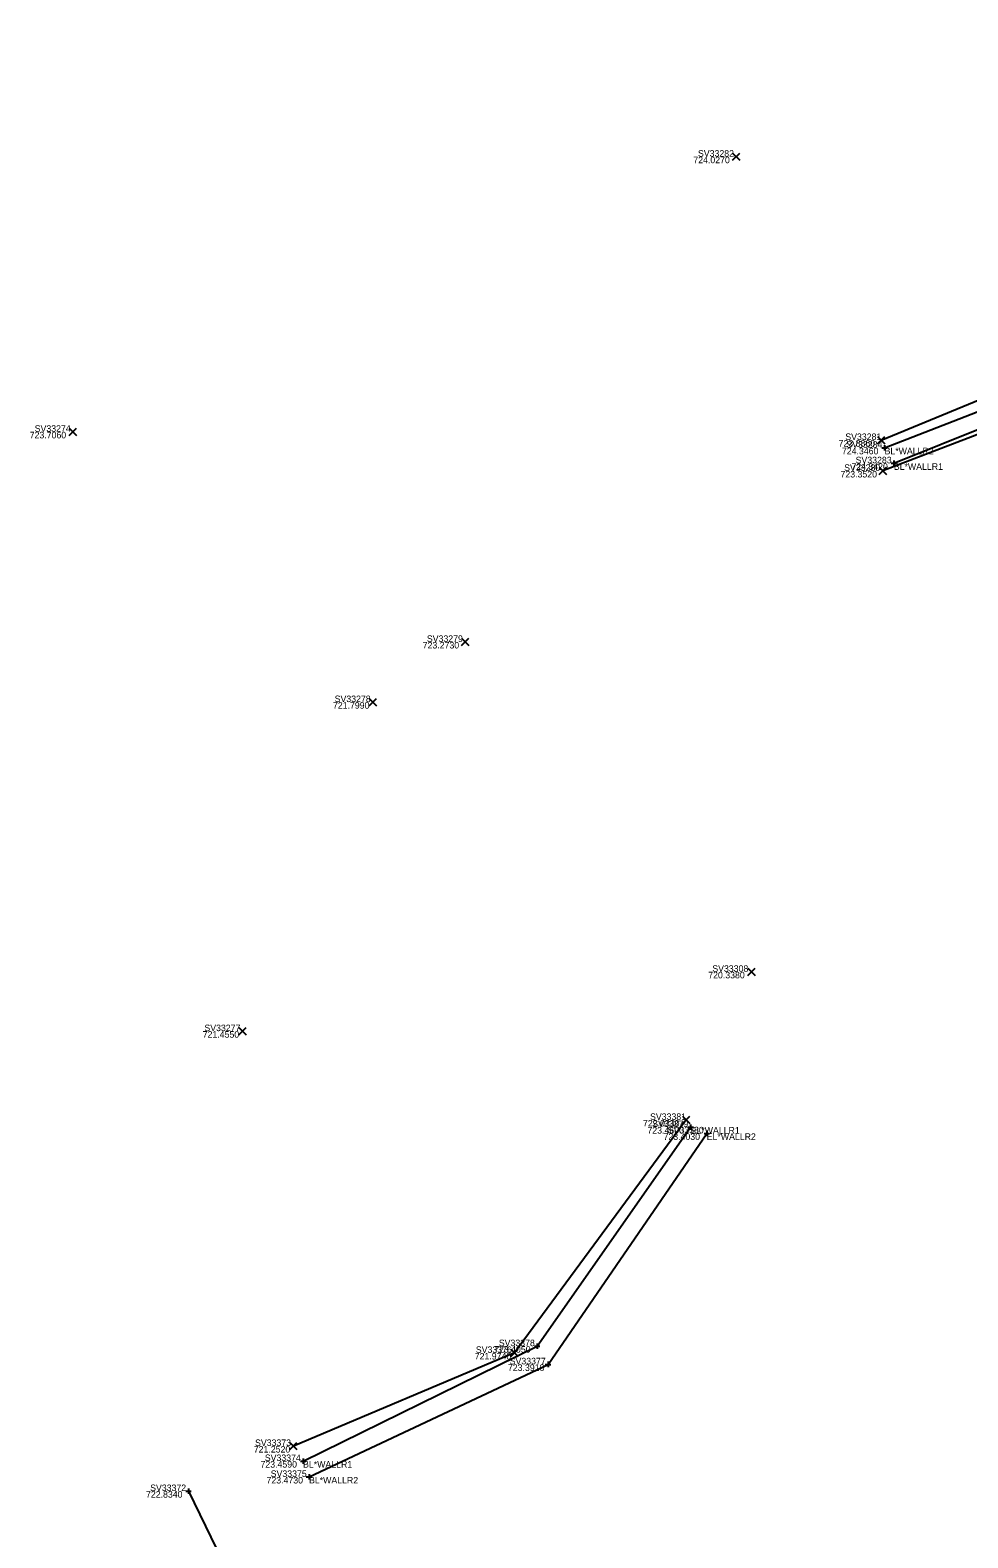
# Model space of a CAD drawing. Extents: x 182090 to 1832865, y 706265 to 714392.
# Drawn here: x 1825837.4 to 1825880.4, y 712737.4 to 712806.6 of the extents above; entities that cross this region are included whole.
import ezdxf

# ---------------------------------------------------------------- set-up
doc = ezdxf.new("R2010")
doc.units = 0
for name, color, linetype in [('RD_X_RR_1', 7, 'Continuous'), ('RD_X_Wall', 7, 'Continuous'), ('SV_X_Break_Lines', 7, 'Continuous'), ('SV_X_Random_Point', 7, 'Continuous'), ('SV_X_Shot_Marker', 7, 'Continuous'), ('SV_X_Text_Comment', 7, 'Continuous'), ('SV_X_Text_Elevation', 7, 'Continuous'), ('SV_X_Text_Name', 7, 'Continuous')]:
    doc.layers.add(name, color=color, linetype=linetype)

msp = doc.modelspace()

# ---------------------------------------------------------------- linework, layer by layer
at = {"layer": 'RD_X_RR_1'}
msp.add_lwpolyline([(1825844.617, 712739.588), (1826106.282, 712204.043)], dxfattribs=at)
at = {"layer": 'RD_X_Wall'}
for points in [[(1825876.549, 712787.476), (1825889.501, 712792.498), (1825891.575, 712793.501), (1825898.392, 712797.167), (1825905.144, 712801.571), (1825911.384, 712806.643)], [(1825876.974, 712786.761), (1825889.852, 712791.943), (1825891.955, 712792.861), (1825898.808, 712796.636), (1825905.449, 712801.016), (1825911.88, 712805.967)], [(1825849.877, 712740.966), (1825860.615, 712746.24), (1825867.653, 712756.296)], [(1825850.149, 712740.237), (1825861.111, 712745.404), (1825868.392, 712756.007)]]:
    msp.add_lwpolyline(points, dxfattribs=at)
at = {"layer": 'SV_X_Break_Lines'}
for points in [[(1825876.391, 712787.83), (1825889.195, 712793.104), (1825898.16, 712797.798), (1825909.116, 712805.348)], [(1825912.106, 712805.479), (1825905.742, 712800.592), (1825898.809, 712796.075), (1825897.825, 712795.633), (1825889.653, 712791.461), (1825876.474, 712786.412)], [(1825867.445, 712756.624), (1825859.576, 712745.928), (1825849.43, 712741.657)]]:
    msp.add_lwpolyline(points, dxfattribs=at)
at = {"layer": 'SV_X_Random_Point'}
for p, q in [((1825869.573, 712800.669), (1825869.907, 712801.003)), ((1825869.573, 712801.003), (1825869.907, 712800.669)), ((1825839.146, 712788.041), (1825839.48, 712788.375)), ((1825839.146, 712788.375), (1825839.48, 712788.041)), ((1825876.224, 712787.663), (1825876.558, 712787.997)), ((1825876.224, 712787.997), (1825876.558, 712787.663)), ((1825876.307, 712786.245), (1825876.641, 712786.579)), ((1825876.307, 712786.579), (1825876.641, 712786.245)), ((1825857.138, 712778.396), (1825857.472, 712778.73)), ((1825857.138, 712778.73), (1825857.472, 712778.396)), ((1825852.909, 712775.634), (1825853.243, 712775.968)), ((1825852.909, 712775.968), (1825853.243, 712775.634)), ((1825870.273, 712763.254), (1825870.607, 712763.588)), ((1825870.273, 712763.588), (1825870.607, 712763.254)), ((1825846.932, 712760.532), (1825847.266, 712760.866)), ((1825846.932, 712760.866), (1825847.266, 712760.532)), ((1825867.278, 712756.457), (1825867.612, 712756.791)), ((1825867.278, 712756.791), (1825867.612, 712756.457)), ((1825859.409, 712745.761), (1825859.743, 712746.095)), ((1825859.409, 712746.095), (1825859.743, 712745.761)), ((1825849.263, 712741.49), (1825849.597, 712741.824)), ((1825849.263, 712741.824), (1825849.597, 712741.49))]:
    msp.add_line(p, q, dxfattribs=at)
at = {"layer": 'SV_X_Shot_Marker'}
for p, q in [((1825876.549, 712787.601), (1825876.549, 712787.351)), ((1825876.424, 712787.476), (1825876.674, 712787.476)), ((1825876.549, 712787.476), (1825876.549, 712787.476)), ((1825876.974, 712786.886), (1825876.974, 712786.636)), ((1825876.849, 712786.761), (1825877.099, 712786.761)), ((1825876.974, 712786.761), (1825876.974, 712786.761)), ((1825867.653, 712756.421), (1825867.653, 712756.171)), ((1825867.528, 712756.296), (1825867.778, 712756.296)), ((1825867.653, 712756.296), (1825867.653, 712756.296)), ((1825868.267, 712756.007), (1825868.517, 712756.007)), ((1825868.392, 712756.132), (1825868.392, 712755.882)), ((1825868.392, 712756.007), (1825868.392, 712756.007)), ((1825860.49, 712746.24), (1825860.74, 712746.24)), ((1825860.615, 712746.365), (1825860.615, 712746.115)), ((1825860.615, 712746.24), (1825860.615, 712746.24)), ((1825860.986, 712745.404), (1825861.236, 712745.404)), ((1825861.111, 712745.529), (1825861.111, 712745.279)), ((1825861.111, 712745.404), (1825861.111, 712745.404)), ((1825849.752, 712740.966), (1825850.002, 712740.966)), ((1825849.877, 712741.091), (1825849.877, 712740.841)), ((1825849.877, 712740.966), (1825849.877, 712740.966)), ((1825850.024, 712740.237), (1825850.274, 712740.237)), ((1825850.149, 712740.362), (1825850.149, 712740.112)), ((1825850.149, 712740.237), (1825850.149, 712740.237)), ((1825844.492, 712739.588), (1825844.742, 712739.588)), ((1825844.617, 712739.713), (1825844.617, 712739.463)), ((1825844.617, 712739.588), (1825844.617, 712739.588))]:
    msp.add_line(p, q, dxfattribs=at)

# ---------------------------------------------------------------- texts
at = {"layer": 'SV_X_Text_Comment'}
for s, p in [('BL*WALLR2', (1825876.549, 712787.176)), ('BL*WALLR1', (1825876.974, 712786.461)), ('EL*WALLR1', (1825867.653, 712755.996)), ('EL*WALLR2', (1825868.392, 712755.707)), ('BL*WALLR1', (1825849.877, 712740.666)), ('BL*WALLR2', (1825850.149, 712739.937))]:
    msp.add_text(s, height=0.3, dxfattribs=at).set_placement(p)
at = {"layer": 'SV_X_Text_Elevation'}
for s, p in [('724.0270', (1825867.777, 712800.536)), ('723.7060', (1825837.338, 712787.908)), ('723.8860', (1825874.44, 712787.53)), ('724.3460', (1825874.593, 712787.176)), ('723.3520', (1825874.528, 712786.112)), ('724.3420', (1825875.028, 712786.461)), ('723.2730', (1825855.363, 712778.263)), ('721.7990', (1825851.248, 712775.501)), ('720.3380', (1825868.461, 712763.121)), ('721.4550', (1825845.273, 712760.399)), ('722.0330', (1825865.47, 712756.324)), ('723.4600', (1825865.671, 712755.996)), ('723.4030', (1825866.41, 712755.707)), ('723.4050', (1825858.638, 712745.94)), ('721.9740', (1825857.75, 712745.628)), ('723.3910', (1825859.273, 712745.104)), ('721.2520', (1825847.616, 712741.357)), ('723.4590', (1825847.924, 712740.666)), ('723.4730', (1825848.2, 712739.937)), ('722.8340', (1825842.673, 712739.288))]:
    msp.add_text(s, height=0.3, dxfattribs=at).set_placement(p)
at = {"layer": 'SV_X_Text_Name'}
for s, p in [('SV33282', (1825867.99, 712800.836)), ('SV33274', (1825837.567, 712788.208)), ('SV33281', (1825874.748, 712787.83)), ('SV33284', (1825874.799, 712787.476)), ('SV33283', (1825875.221, 712786.761)), ('SV33280', (1825874.695, 712786.412)), ('SV33279', (1825855.555, 712778.563)), ('SV33278', (1825851.326, 712775.801)), ('SV33308', (1825868.647, 712763.421)), ('SV33277', (1825845.351, 712760.699)), ('SV33381', (1825865.792, 712756.624)), ('SV33379', (1825865.893, 712756.296)), ('SV33380', (1825866.604, 712756.007)), ('SV33376', (1825857.8, 712745.928)), ('SV33378', (1825858.855, 712746.24)), ('SV33377', (1825859.354, 712745.404)), ('SV33373', (1825847.673, 712741.657)), ('SV33374', (1825848.122, 712740.966)), ('SV33375', (1825848.392, 712740.237)), ('SV33372', (1825842.862, 712739.588))]:
    msp.add_text(s, height=0.3, dxfattribs=at).set_placement(p)

doc.saveas('drawing.dxf')
